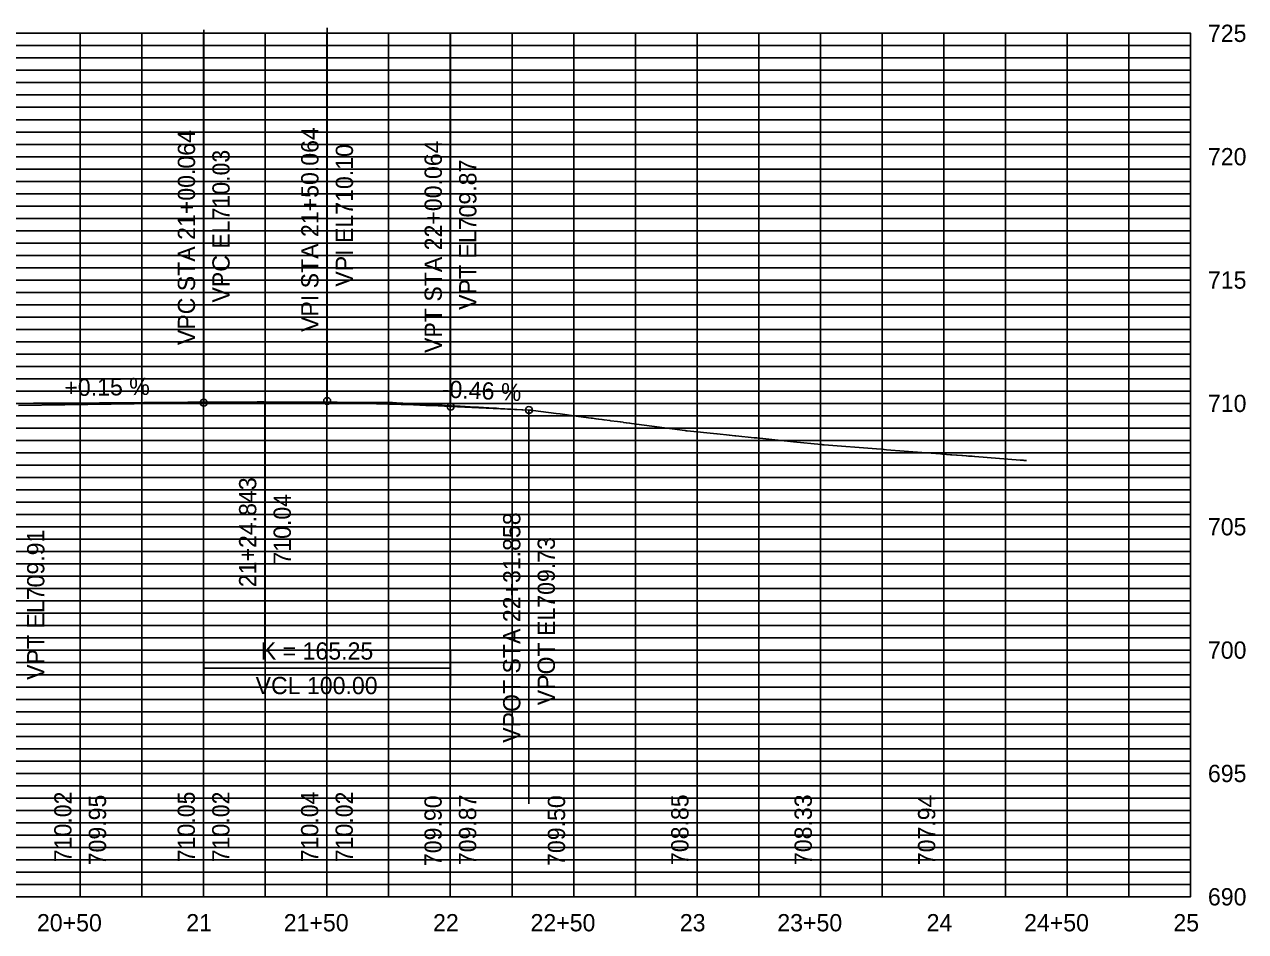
# Model space of a CAD drawing. Extents: x 599407 to 600507, y 234180 to 234548.
# Drawn here: x 600011.7 to 600506.6, y 234179.9 to 234547.6 of the extents above; entities that cross this region are included whole.
import ezdxf

# ---------------------------------------------------------------- set-up
doc = ezdxf.new("R2010")
doc.units = 0
for name, color, linetype in [('E_PROF_Grid', 7, 'Continuous'), ('E_PROF_GridMin', 7, 'Continuous'), ('P_E_XS_Ground', 7, 'Continuous'), ('P_PROF', 7, 'Continuous'), ('P_PROF_Grades', 7, 'Continuous'), ('P_PROF_VPINotes', 7, 'Continuous'), ('PLT_Sheet_Info', 7, 'Continuous')]:
    doc.layers.add(name, color=color, linetype=linetype)

msp = doc.modelspace()

# ---------------------------------------------------------------- linework, layer by layer
at = {"layer": 'E_PROF_Grid'}
for p, q in [((600034.31, 234193.96), (600034.31, 234543.96)), ((600059.31, 234193.96), (600059.31, 234543.96)), ((600084.31, 234193.96), (600084.31, 234543.96)), ((600109.31, 234193.96), (600109.31, 234543.96)), ((600134.31, 234193.96), (600134.31, 234543.96)), ((600159.31, 234193.96), (600159.31, 234543.96)), ((600184.31, 234193.96), (600184.31, 234543.96)), ((600209.31, 234193.96), (600209.31, 234543.96)), ((600234.31, 234193.96), (600234.31, 234543.96)), ((600259.31, 234193.96), (600259.31, 234543.96)), ((600284.31, 234193.96), (600284.31, 234543.96)), ((600309.31, 234193.96), (600309.31, 234543.96)), ((600334.31, 234193.96), (600334.31, 234543.96)), ((600359.31, 234193.96), (600359.31, 234543.96)), ((600384.31, 234193.96), (600384.31, 234543.96)), ((600409.31, 234193.96), (600409.31, 234543.96)), ((600434.31, 234193.96), (600434.31, 234543.96)), ((600459.31, 234193.96), (600459.31, 234543.96)), ((599434.31, 234518.96), (600484.31, 234518.96)), ((599434.31, 234493.96), (600484.31, 234493.96)), ((599434.31, 234468.96), (600484.31, 234468.96)), ((599434.31, 234443.96), (600484.31, 234443.96)), ((599434.31, 234418.96), (600484.31, 234418.96)), ((599434.31, 234393.96), (600484.31, 234393.96)), ((599434.31, 234368.96), (600484.31, 234368.96)), ((599434.31, 234343.96), (600484.31, 234343.96)), ((599434.31, 234318.96), (600484.31, 234318.96)), ((599434.31, 234293.96), (600484.31, 234293.96)), ((599434.31, 234268.96), (600484.31, 234268.96)), ((599434.31, 234243.96), (600484.31, 234243.96)), ((599434.31, 234218.96), (600484.31, 234218.96))]:
    msp.add_line(p, q, dxfattribs=at)
at = {"layer": 'E_PROF_GridMin'}
for p, q in [((599434.31, 234538.96), (600484.31, 234538.96)), ((599434.31, 234533.96), (600484.31, 234533.96)), ((599434.31, 234528.96), (600484.31, 234528.96)), ((599434.31, 234523.96), (600484.31, 234523.96)), ((599434.31, 234513.96), (600484.31, 234513.96)), ((599434.31, 234508.96), (600484.31, 234508.96)), ((599434.31, 234503.96), (600484.31, 234503.96)), ((599434.31, 234498.96), (600484.31, 234498.96)), ((599434.31, 234488.96), (600484.31, 234488.96)), ((599434.31, 234483.96), (600484.31, 234483.96)), ((599434.31, 234478.96), (600484.31, 234478.96)), ((599434.31, 234473.96), (600484.31, 234473.96)), ((599434.31, 234463.96), (600484.31, 234463.96)), ((599434.31, 234458.96), (600484.31, 234458.96)), ((599434.31, 234453.96), (600484.31, 234453.96)), ((599434.31, 234448.96), (600484.31, 234448.96)), ((599434.31, 234438.96), (600484.31, 234438.96)), ((599434.31, 234433.96), (600484.31, 234433.96)), ((599434.31, 234428.96), (600484.31, 234428.96)), ((599434.31, 234423.96), (600484.31, 234423.96)), ((599434.31, 234413.96), (600484.31, 234413.96)), ((599434.31, 234408.96), (600484.31, 234408.96)), ((599434.31, 234403.96), (600484.31, 234403.96)), ((599434.31, 234398.96), (600484.31, 234398.96)), ((599434.31, 234388.96), (600484.31, 234388.96)), ((599434.31, 234383.96), (600484.31, 234383.96)), ((599434.31, 234378.96), (600484.31, 234378.96)), ((599434.31, 234373.96), (600484.31, 234373.96)), ((599434.31, 234363.96), (600484.31, 234363.96)), ((599434.31, 234358.96), (600484.31, 234358.96)), ((599434.31, 234353.96), (600484.31, 234353.96)), ((599434.31, 234348.96), (600484.31, 234348.96)), ((599434.31, 234338.96), (600484.31, 234338.96)), ((599434.31, 234333.96), (600484.31, 234333.96)), ((599434.31, 234328.96), (600484.31, 234328.96)), ((599434.31, 234323.96), (600484.31, 234323.96)), ((599434.31, 234313.96), (600484.31, 234313.96)), ((599434.31, 234308.96), (600484.31, 234308.96)), ((599434.31, 234303.96), (600484.31, 234303.96)), ((599434.31, 234298.96), (600484.31, 234298.96)), ((599434.31, 234288.96), (600484.31, 234288.96)), ((599434.31, 234283.96), (600484.31, 234283.96)), ((599434.31, 234278.96), (600484.31, 234278.96)), ((599434.31, 234273.96), (600484.31, 234273.96)), ((599434.31, 234263.96), (600484.31, 234263.96)), ((599434.31, 234258.96), (600484.31, 234258.96)), ((599434.31, 234253.96), (600484.31, 234253.96)), ((599434.31, 234248.96), (600484.31, 234248.96)), ((599434.31, 234238.96), (600484.31, 234238.96)), ((599434.31, 234233.96), (600484.31, 234233.96)), ((599434.31, 234228.96), (600484.31, 234228.96)), ((599434.31, 234223.96), (600484.31, 234223.96)), ((599434.31, 234213.96), (600484.31, 234213.96)), ((599434.31, 234208.96), (600484.31, 234208.96)), ((599434.31, 234203.96), (600484.31, 234203.96)), ((599434.31, 234198.96), (600484.31, 234198.96))]:
    msp.add_line(p, q, dxfattribs=at)
at = {"layer": 'P_E_XS_Ground'}
for p, q in [((600015.44, 234394.09), (600015.44, 234394.09)), ((600015.69, 234394.09), (600015.69, 234394.09)), ((600016.19, 234394.07), (600016.19, 234394.07)), ((600022, 234394.07), (600022, 234394.07)), ((600024.38, 234394.1), (600024.38, 234394.1)), ((600078, 234394.45), (600078, 234394.45)), ((600078.44, 234394.43), (600078.44, 234394.43)), ((600106.06, 234394.59), (600106.06, 234394.6)), ((600106.69, 234394.59), (600106.69, 234394.59)), ((600107.69, 234394.56), (600107.69, 234394.56)), ((600108.06, 234394.56), (600108.06, 234394.56)), ((600108.25, 234394.56), (600108.25, 234394.56)), ((600108.69, 234394.56), (600108.69, 234394.56)), ((600120.81, 234394.5), (600120.81, 234394.5)), ((600121.06, 234394.5), (600121.06, 234394.5)), ((600123.19, 234394.48), (600123.19, 234394.48)), ((600123.25, 234394.48), (600123.25, 234394.48)), ((600129.25, 234394.43), (600129.25, 234394.43)), ((600129.38, 234394.43), (600129.38, 234394.43)), ((600130.31, 234394.43), (600130.31, 234394.43)), ((600130.31, 234394.43), (600130.31, 234394.43)), ((600130.44, 234394.43), (600130.44, 234394.43)), ((600131.25, 234394.43), (600131.25, 234394.43)), ((600131.25, 234394.43), (600131.25, 234394.43)), ((600131.38, 234394.43), (600131.38, 234394.43)), ((600132.44, 234394.42), (600132.44, 234394.42)), ((600132.44, 234394.42), (600132.44, 234394.42)), ((600132.62, 234394.42), (600132.62, 234394.42)), ((600133.38, 234394.42), (600133.38, 234394.42)), ((600133.38, 234394.42), (600133.38, 234394.42)), ((600133.5, 234394.42), (600133.5, 234394.42)), ((600134.25, 234394.42), (600134.25, 234394.42)), ((600134.25, 234394.42), (600134.25, 234394.42)), ((600134.38, 234394.42), (600134.38, 234394.42)), ((600135.69, 234394.4), (600135.69, 234394.4)), ((600135.75, 234394.4), (600135.75, 234394.4)), ((600135.94, 234394.4), (600135.94, 234394.4)), ((600137.38, 234394.4), (600137.38, 234394.4)), ((600137.38, 234394.4), (600137.38, 234394.4)), ((600137.62, 234394.4), (600137.62, 234394.4)), ((600138.31, 234394.39), (600138.31, 234394.39)), ((600138.31, 234394.39), (600138.31, 234394.39)), ((600138.44, 234394.39), (600138.44, 234394.39)), ((600142.81, 234394.37), (600142.81, 234394.37)), ((600142.88, 234394.37), (600142.88, 234394.37)), ((600143.56, 234394.37), (600143.56, 234394.37)), ((600148.38, 234394.34), (600148.38, 234394.34)), ((600150.88, 234394.32), (600150.88, 234394.32)), ((600160.94, 234394.26), (600160.94, 234394.26)), ((600161.69, 234394.23), (600161.69, 234394.23)), ((600161.88, 234394.23), (600161.88, 234394.23)), ((600162.12, 234394.21), (600162.12, 234394.21)), ((600162.56, 234394.2), (600162.56, 234394.2)), ((600180.5, 234393.21), (600180.5, 234393.21)), ((600180.94, 234393.2), (600180.94, 234393.2)), ((600182.12, 234393.14), (600182.12, 234393.14)), ((600182.12, 234393.12), (600182.12, 234393.14)), ((600182.31, 234393.12), (600182.31, 234393.12)), ((600187.38, 234392.84), (600187.38, 234392.84)), ((600187.5, 234392.84), (600187.5, 234392.84)), ((600188.25, 234392.81), (600188.25, 234392.81)), ((600192.38, 234392.57), (600192.38, 234392.57)), ((600195.75, 234392.39), (600195.75, 234392.39)), ((600202, 234392.04), (600202, 234392.04)), ((600203, 234391.98), (600203, 234391.98)), ((600203.94, 234391.92), (600203.94, 234391.92)), ((600203.94, 234391.92), (600203.94, 234391.92)), ((600216.19, 234391.25), (600216.19, 234391.25)), ((600216.44, 234391.23), (600216.44, 234391.23)), ((600216.62, 234391.21), (600216.62, 234391.21)), ((600216.75, 234391.2), (600216.75, 234391.2)), ((600216.81, 234391.2), (600216.81, 234391.2)), ((600216.94, 234391.18), (600216.94, 234391.18)), ((600217.19, 234391.17), (600217.19, 234391.17)), ((600217.94, 234391.12), (600217.94, 234391.12)), ((600227.19, 234389.89), (600227.19, 234389.9)), ((600228.81, 234389.68), (600228.81, 234389.68)), ((600236.31, 234388.68), (600236.31, 234388.68)), ((600241.38, 234388.01), (600241.38, 234388.01)), ((600241.94, 234387.93), (600241.94, 234387.93)), ((600243.25, 234387.76), (600243.25, 234387.76)), ((600243.31, 234387.75), (600243.31, 234387.75)), ((600243.44, 234387.73), (600243.44, 234387.73)), ((600244.31, 234387.6), (600244.31, 234387.62)), ((600244.31, 234387.62), (600244.31, 234387.62)), ((600244.44, 234387.6), (600244.44, 234387.6)), ((600245.69, 234387.43), (600245.69, 234387.43)), ((600245.69, 234387.43), (600245.69, 234387.43)), ((600245.81, 234387.42), (600245.81, 234387.42)), ((600246.5, 234387.32), (600246.5, 234387.32)), ((600246.5, 234387.32), (600246.5, 234387.32)), ((600246.62, 234387.31), (600246.62, 234387.31)), ((600249, 234387), (600249, 234387)), ((600249.06, 234386.98), (600249.06, 234386.98)), ((600249.25, 234386.95), (600249.25, 234386.95)), ((600252.12, 234386.57), (600252.12, 234386.57)), ((600252.12, 234386.57), (600252.12, 234386.57)), ((600253.19, 234386.43), (600253.19, 234386.43)), ((600253.19, 234386.43), (600253.19, 234386.43)), ((600253.31, 234386.42), (600253.31, 234386.42)), ((600254.38, 234386.28), (600254.38, 234386.28)), ((600254.38, 234386.28), (600254.38, 234386.28)), ((600254.5, 234386.26), (600254.5, 234386.26)), ((600255.56, 234386.12), (600255.56, 234386.12)), ((600255.56, 234386.12), (600255.56, 234386.12)), ((600255.69, 234386.1), (600255.69, 234386.1)), ((600256.94, 234385.93), (600256.94, 234385.93)), ((600256.94, 234385.93), (600256.94, 234385.93)), ((600257.06, 234385.92), (600257.06, 234385.92)), ((600257.69, 234385.84), (600257.69, 234385.84)), ((600257.69, 234385.84), (600257.69, 234385.84)), ((600257.69, 234385.82), (600257.69, 234385.82)), ((600279.31, 234382.96), (600279.31, 234382.96)), ((600279.5, 234382.95), (600279.5, 234382.95)), ((600279.56, 234382.93), (600279.56, 234382.93)), ((600279.62, 234382.92), (600279.62, 234382.93)), ((600279.81, 234382.9), (600279.81, 234382.9)), ((600280, 234382.87), (600280, 234382.89)), ((600280.06, 234382.87), (600280.06, 234382.87)), ((600280.12, 234382.87), (600280.12, 234382.87)), ((600280.19, 234382.85), (600280.19, 234382.85)), ((600280.25, 234382.84), (600280.25, 234382.84)), ((600292.31, 234381.6), (600292.31, 234381.6)), ((600292.44, 234381.59), (600292.44, 234381.59)), ((600297.38, 234381.09), (600297.38, 234381.09)), ((600297.44, 234381.07), (600297.44, 234381.07)), ((600299.56, 234380.87), (600299.56, 234380.87)), ((600299.56, 234380.85), (600299.56, 234380.85)), ((600299.62, 234380.85), (600299.62, 234380.85)), ((600299.94, 234380.82), (600299.94, 234380.82)), ((600299.94, 234380.82), (600299.94, 234380.82)), ((600307.44, 234380.04), (600307.44, 234380.04)), ((600307.5, 234380.04), (600307.5, 234380.04)), ((600307.81, 234380.01), (600307.81, 234380.01)), ((600308.56, 234379.93), (600308.56, 234379.93)), ((600313.38, 234379.43), (600313.38, 234379.43)), ((600323.38, 234378.4), (600323.38, 234378.4)), ((600334.62, 234377.25), (600334.62, 234377.26)), ((600334.94, 234377.23), (600334.94, 234377.23)), ((600335, 234377.23), (600335, 234377.23)), ((600335.06, 234377.21), (600335.06, 234377.21)), ((600335.19, 234377.2), (600335.19, 234377.21)), ((600335.19, 234377.21), (600335.19, 234377.21)), ((600335.25, 234377.2), (600335.25, 234377.2)), ((600335.31, 234377.2), (600335.31, 234377.2)), ((600335.38, 234377.2), (600335.38, 234377.2)), ((600335.81, 234377.17), (600335.81, 234377.17)), ((600357, 234375.51), (600357, 234375.51)), ((600359.06, 234375.35), (600359.06, 234375.35)), ((600360.12, 234375.28), (600360.12, 234375.28)), ((600361, 234375.2), (600361, 234375.2)), ((600375.44, 234374.07), (600375.44, 234374.07)), ((600382.88, 234373.5), (600382.88, 234373.5)), ((600383.81, 234373.43), (600383.81, 234373.43)), ((600387.06, 234373.17), (600387.06, 234373.18)), ((600387.12, 234373.17), (600387.12, 234373.17)), ((600387.5, 234373.14), (600387.5, 234373.14)), ((600389.44, 234373), (600389.44, 234373)), ((600389.5, 234372.98), (600389.5, 234372.98)), ((600389.69, 234372.96), (600389.69, 234372.96)), ((600391.62, 234372.82), (600391.62, 234372.82)), ((600391.69, 234372.81), (600391.69, 234372.82)), ((600391.88, 234372.79), (600391.88, 234372.79)), ((600393.31, 234372.68), (600393.31, 234372.68)), ((600393.31, 234372.68), (600393.31, 234372.68)), ((600393.5, 234372.67), (600393.5, 234372.67)), ((600394.25, 234372.62), (600394.25, 234372.62)), ((600394.25, 234372.6), (600394.25, 234372.6)), ((600394.38, 234372.6), (600394.38, 234372.6)), ((600395.56, 234372.51), (600395.56, 234372.51)), ((600395.62, 234372.51), (600395.62, 234372.51)), ((600395.75, 234372.5), (600395.75, 234372.5)), ((600396.69, 234372.42), (600396.69, 234372.43)), ((600396.69, 234372.42), (600396.69, 234372.42)), ((600396.81, 234372.42), (600396.81, 234372.42)), ((600415.19, 234370.98), (600415.19, 234370.98)), ((600415.69, 234370.95), (600415.69, 234370.95)), ((600415.88, 234370.93), (600415.88, 234370.93)), ((600416.38, 234370.89), (600416.38, 234370.89)), ((600416.81, 234370.85), (600416.81, 234370.85)), ((600417.31, 234370.81), (600417.31, 234370.81)), ((600417.75, 234370.78), (600417.75, 234370.78))]:
    msp.add_line(p, q, dxfattribs=at)
msp.add_lwpolyline([(599997.56, 234393.71), (600015.44, 234394.09), (600015.69, 234394.09), (600016.19, 234394.07), (600022, 234394.07), (600024.38, 234394.1), (600078, 234394.45), (600078.44, 234394.43), (600106.06, 234394.59), (600106.69, 234394.59), (600107.69, 234394.56), (600108.06, 234394.56), (600108.25, 234394.56), (600108.69, 234394.56), (600120.81, 234394.5), (600121.06, 234394.5), (600123.19, 234394.48), (600123.25, 234394.48), (600129.25, 234394.43), (600129.38, 234394.43), (600130.31, 234394.43), (600130.31, 234394.43), (600130.44, 234394.43), (600131.25, 234394.43), (600131.25, 234394.43), (600131.38, 234394.43), (600132.44, 234394.42), (600132.44, 234394.42), (600132.62, 234394.42), (600133.38, 234394.42), (600133.38, 234394.42), (600133.5, 234394.42), (600134.25, 234394.42), (600134.25, 234394.42), (600134.38, 234394.42), (600135.69, 234394.4), (600135.75, 234394.4), (600135.94, 234394.4), (600137.38, 234394.4), (600137.38, 234394.4), (600137.62, 234394.4), (600138.31, 234394.39), (600138.31, 234394.39), (600138.44, 234394.39), (600142.81, 234394.37), (600142.88, 234394.37), (600143.56, 234394.37), (600148.38, 234394.34), (600150.88, 234394.32), (600160.94, 234394.26), (600161.69, 234394.23), (600161.88, 234394.23), (600162.12, 234394.21), (600162.56, 234394.2), (600180.5, 234393.21), (600180.94, 234393.2), (600182.12, 234393.14), (600182.12, 234393.12), (600182.31, 234393.12), (600187.38, 234392.84), (600187.5, 234392.84), (600188.25, 234392.81), (600192.38, 234392.57), (600195.75, 234392.39), (600202, 234392.04), (600203, 234391.98), (600203.94, 234391.92), (600203.94, 234391.92), (600216.19, 234391.25), (600216.44, 234391.23), (600216.62, 234391.21), (600216.75, 234391.2), (600216.81, 234391.2), (600216.94, 234391.18), (600217.19, 234391.17), (600217.94, 234391.12), (600227.19, 234389.89), (600228.81, 234389.68), (600236.31, 234388.68), (600241.38, 234388.01), (600241.94, 234387.93), (600243.25, 234387.76), (600243.31, 234387.75), (600243.44, 234387.73), (600244.31, 234387.62), (600244.31, 234387.6), (600244.44, 234387.6), (600245.69, 234387.43), (600245.69, 234387.43), (600245.81, 234387.42), (600246.5, 234387.32), (600246.5, 234387.32), (600246.62, 234387.31), (600249, 234387), (600249.06, 234386.98), (600249.25, 234386.95), (600252.12, 234386.57), (600252.12, 234386.57), (600253.19, 234386.43), (600253.19, 234386.43), (600253.31, 234386.42), (600254.38, 234386.28), (600254.38, 234386.28), (600254.5, 234386.26), (600255.56, 234386.12), (600255.56, 234386.12), (600255.69, 234386.1), (600256.94, 234385.93), (600256.94, 234385.93), (600257.06, 234385.92), (600257.69, 234385.84), (600257.69, 234385.84), (600257.69, 234385.82), (600279.31, 234382.96), (600279.5, 234382.95), (600279.56, 234382.93), (600279.62, 234382.92), (600279.81, 234382.9), (600280, 234382.87), (600280.06, 234382.87), (600280.12, 234382.87), (600280.19, 234382.85), (600280.25, 234382.84), (600292.31, 234381.6), (600292.44, 234381.59), (600297.38, 234381.09), (600297.44, 234381.07), (600299.56, 234380.87), (600299.56, 234380.85), (600299.62, 234380.85), (600299.94, 234380.82), (600299.94, 234380.82), (600307.44, 234380.04), (600307.5, 234380.04), (600307.81, 234380.01), (600308.56, 234379.93), (600313.38, 234379.43), (600323.38, 234378.4), (600334.62, 234377.25), (600334.94, 234377.23), (600335, 234377.23), (600335.06, 234377.21), (600335.19, 234377.21), (600335.19, 234377.2), (600335.25, 234377.2), (600335.31, 234377.2), (600335.38, 234377.2), (600335.81, 234377.17), (600357, 234375.51), (600359.06, 234375.35), (600360.12, 234375.28), (600361, 234375.2), (600375.44, 234374.07), (600382.88, 234373.5), (600383.81, 234373.43), (600387.06, 234373.17), (600387.12, 234373.17), (600387.5, 234373.14), (600389.44, 234373), (600389.5, 234372.98), (600389.69, 234372.96), (600391.62, 234372.82), (600391.69, 234372.81), (600391.88, 234372.79), (600393.31, 234372.68), (600393.31, 234372.68), (600393.5, 234372.67), (600394.25, 234372.62), (600394.25, 234372.6), (600394.38, 234372.6), (600395.56, 234372.51), (600395.62, 234372.51), (600395.75, 234372.5), (600396.69, 234372.42), (600396.69, 234372.42), (600396.81, 234372.42), (600415.19, 234370.98), (600415.69, 234370.95), (600415.88, 234370.93), (600416.38, 234370.89), (600416.81, 234370.85), (600417.31, 234370.81), (600417.75, 234370.78)], dxfattribs=at)
at = {"layer": 'P_PROF'}
msp.add_lwpolyline([(600009.31, 234393.09), (600084.38, 234394.21), (600089.38, 234394.28), (600094.38, 234394.34), (600099.38, 234394.37), (600104.38, 234394.4), (600109.38, 234394.4), (600114.38, 234394.39), (600119.38, 234394.37), (600124.38, 234394.34), (600129.38, 234394.28), (600134.38, 234394.21), (600139.38, 234394.12), (600144.38, 234394.03), (600149.38, 234393.92), (600154.38, 234393.78), (600159.38, 234393.64), (600164.38, 234393.48), (600169.38, 234393.31), (600174.38, 234393.12), (600179.38, 234392.92), (600184.38, 234392.68), (600184.38, 234392.68), (600184.38, 234392.68), (600216.19, 234391.25)], dxfattribs=at)
for centre in [(600084.41, 234394.21), (600134.41, 234394.96), (600184.41, 234392.68), (600216.16, 234391.23)]:
    msp.add_circle(centre, 1.41, dxfattribs=at)
at = {"layer": 'P_PROF_Grades'}
for p, q in [((600034.31, 234193.96), (600034.31, 234252.76)), ((600034.31, 234193.96), (600034.31, 234252.76)), ((600084.31, 234193.96), (600084.31, 234252.76)), ((600084.31, 234193.96), (600084.31, 234252.76)), ((600134.31, 234193.96), (600134.31, 234252.76)), ((600134.31, 234193.96), (600134.31, 234252.76)), ((600184.31, 234193.96), (600184.31, 234252.76)), ((600184.31, 234193.96), (600184.31, 234252.76)), ((600234.31, 234193.96), (600234.31, 234252.76)), ((600284.31, 234193.96), (600284.31, 234252.76)), ((600334.31, 234193.96), (600334.31, 234252.76)), ((600384.31, 234193.96), (600384.31, 234252.76))]:
    msp.add_line(p, q, dxfattribs=at)
at = {"layer": 'P_PROF_VPINotes'}
for p, q in [((600084.38, 234394.21), (600084.38, 234545.42)), ((600134.38, 234394.96), (600134.38, 234546.17)), ((600184.38, 234392.68), (600184.38, 234543.89)), ((600109.19, 234394.4), (600109.19, 234293.6)), ((600216.19, 234391.25), (600216.19, 234231.64)), ((600084.38, 234279.6), (600084.38, 234293.6)), ((600184.38, 234279.6), (600184.38, 234293.6)), ((600084.38, 234286.6), (600184.38, 234286.6))]:
    msp.add_line(p, q, dxfattribs=at)
at = {"layer": 'PLT_Sheet_Info'}
msp.add_lwpolyline([(599434.31, 234193.96), (600484.31, 234193.96), (600484.31, 234543.96), (599434.31, 234543.96), (599434.31, 234193.96)], dxfattribs=at)

# ---------------------------------------------------------------- texts
at = {"layer": 'P_PROF_Grades'}
for s, p in [('725', (600491.31, 234540.46)), ('720', (600491.31, 234490.46)), ('715', (600491.31, 234440.46)), ('710', (600491.31, 234390.46)), ('705', (600491.31, 234340.46)), ('700', (600491.31, 234290.46)), ('695', (600491.31, 234240.46)), ('690', (600491.31, 234190.46)), ('20+50', (600016.81, 234179.96)), ('21', (600077.31, 234179.96)), ('21+50', (600116.81, 234179.96)), ('22', (600177.31, 234179.96)), ('22+50', (600216.81, 234179.96)), ('23', (600277.31, 234179.96)), ('23+50', (600316.81, 234179.96)), ('24', (600377.31, 234179.96)), ('24+50', (600416.81, 234179.96)), ('25', (600477.31, 234179.96))]:
    msp.add_text(s, height=7, dxfattribs=at).set_placement(p)
for s, rotation, p in [('+0.15 %', 0.8591, (600027.97, 234396.87)), ('-0.46 %', 357.3937, (600180.73, 234396.36)), ('710.02', 90, (600030.81, 234207.99)), ('710.05', 90, (600080.81, 234207.99)), ('710.02', 90, (600094.81, 234207.99)), ('710.04', 90, (600130.81, 234207.99)), ('710.02', 90, (600144.81, 234207.99)), ('709.95', 90, (600044.81, 234206.73)), ('709.90', 90, (600180.81, 234206.42)), ('709.87', 90, (600194.81, 234206.78)), ('709.50', 90, (600230.81, 234206.48)), ('708.85', 90, (600280.81, 234206.84)), ('708.33', 90, (600330.81, 234206.84)), ('707.94', 90, (600380.81, 234206.78))]:
    msp.add_text(s, height=7, rotation=rotation, dxfattribs=at).set_placement(p)
at = {"layer": 'P_PROF_VPINotes'}
for s, rotation, p in [('VPC STA 21+00.064', 90, (600080.88, 234417.58)), ('VPI STA 21+50.064', 90, (600130.88, 234422.9)), ('VPI EL710.10', 90, (600144.88, 234441.28)), ('VPT STA 22+00.064', 90, (600180.88, 234414.39)), ('VPC EL710.03', 90, (600094.88, 234434.83)), ('VPT EL709.87', 90, (600194.88, 234431.86)), ('21+24.843', 90, (600105.69, 234319.47)), ('710.04', 90, (600119.69, 234328.62)), ('VPOT STA 22+31.858', 90, (600212.69, 234256.39)), ('VPT EL709.91', 90, (600019.81, 234281.89)), ('VPOT EL709.73', 90, (600226.69, 234271.6)), ('K = 165.25', 0, (600107.54, 234290.1)), ('VCL 100.00', 0, (600105.41, 234276.1))]:
    msp.add_text(s, height=7, rotation=rotation, dxfattribs=at).set_placement(p)

doc.saveas('drawing.dxf')
